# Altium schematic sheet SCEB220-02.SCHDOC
size A3
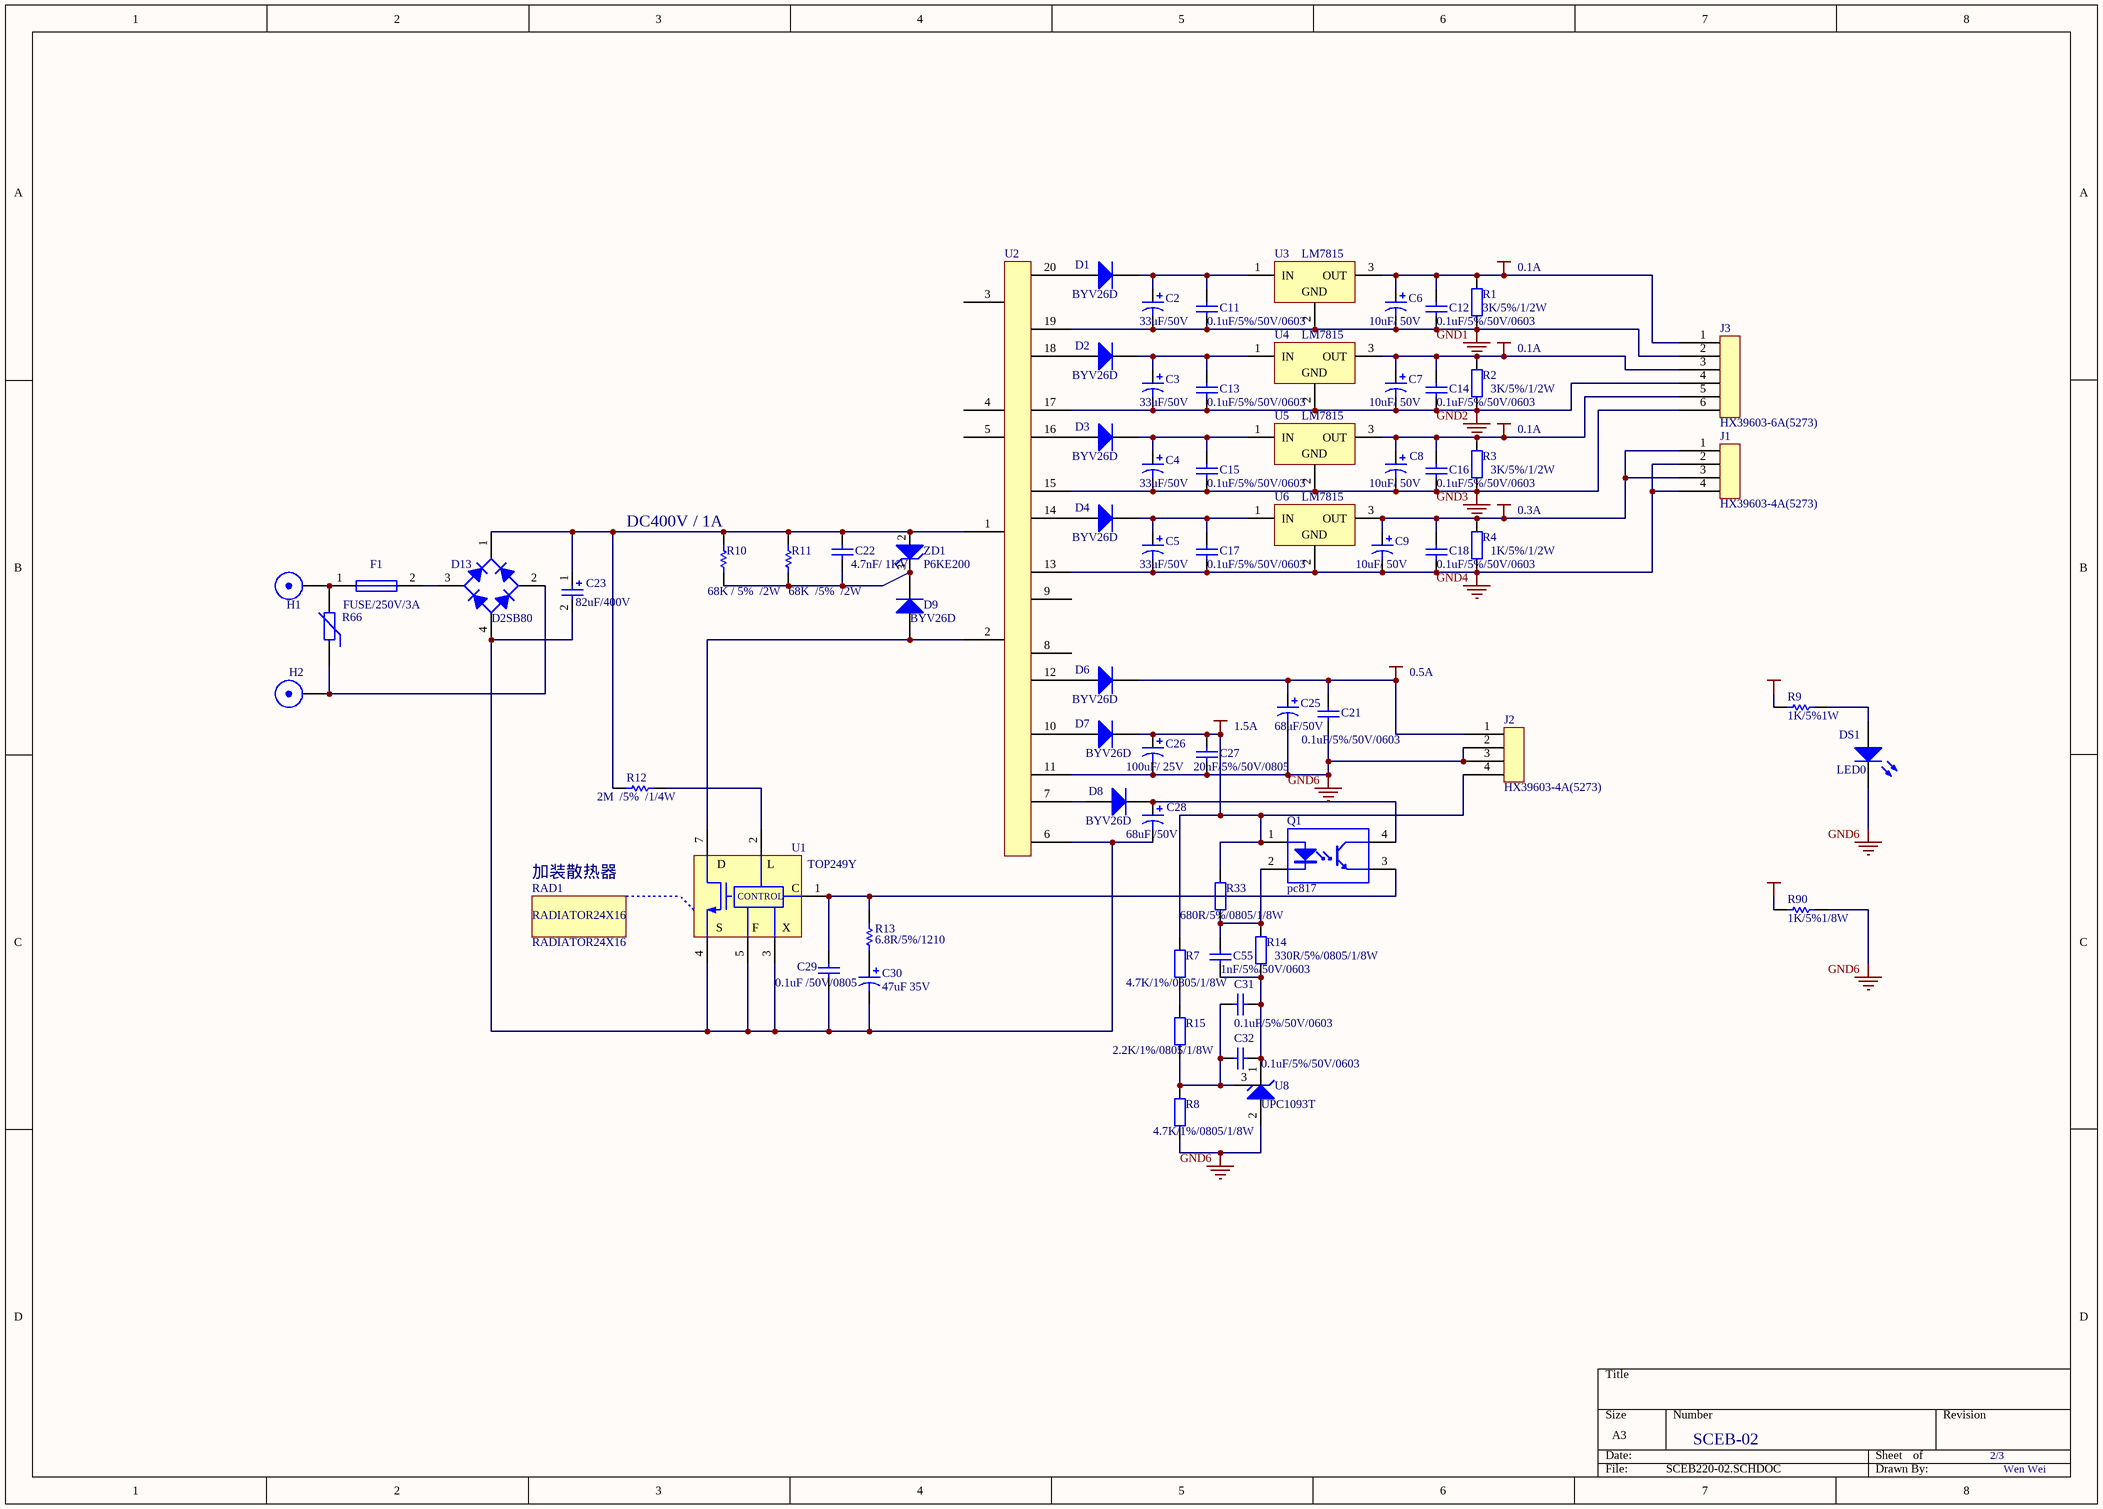
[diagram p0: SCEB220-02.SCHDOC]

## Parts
C2  value 33uF/50V  [CAP2.0-5X11]
C3  value 33uF/50V  [CAP2.0-5X11]
C4  value 33uF/50V  [CAP2.0-5X11]
C5  value 33uF/50V  [CAP2.0-5X11]
C6  10uF/ 50V  [CAP2.0-5X11]
C7  10uF/ 50V  [CAP2.0-5X11]
C8  10uF/ 50V  [CAP2.0-5X11]
C9  10uF/ 50V  [CAP2.0-5X11]
C11  0.1uF/50V/0603  [CR1608-0603]  (value not drawn)
C12  0.1uF/50V/0603  [CC2012-0805]  (value not drawn)
C13  0.1uF/50V/0603  [CC2012-0805]  (value not drawn)
C14  0.1uF/50V/0603  [CC2012-0805]  (value not drawn)
C15  0.1uF/50V/0603  [CC2012-0805]  (value not drawn)
C16  0.1uF/50V/0603  [CC2012-0805]  (value not drawn)
C17  0.1uF/50V/0603  [CC2012-0805]  (value not drawn)
C18  0.1uF/50V/0603  [CC2012-0805]  (value not drawn)
C21  0.1uF/50V/0603  [CC2012-0805]  (value not drawn)
C22  4.7nF/ 1KV  [RAD-0.3]
C23  URZ2G270MHH3  [CAPP10-22x25]  (value not drawn)
C25  68uF/50V  [CAP3.5-8X11.5]
C26  100uF/ 25V  [CAP3.5-8X11.5]
C27  (no value)  [CC2012-0805]
C28  68uF /50V  [CAP3.5-8X11.5]
C29  0.1uF /50V/0805  [CC2012-0805]
C30  47uF 35V  [CAPP2-5x11]
C31  0.1uF/5%/50V/0603  [CC2012-0805]
C32  0.1uF/5%/50V/0603  [CC2012-0805]
C55  1nF/5%/50V/0603  [CC2012-0805]
D1  BYV26D  [DIO7.1-3.9x1.9]
D2  BYV26D  [DIO7.1-3.9x1.9]
D3  BYV26D  [DIO7.1-3.9x1.9]
D4  BYV26D  [DIO7.1-3.9x1.9]
D6  BYV26D  [DIO7.1-3.9x1.9]
D7  BYV26D  [DIO7.1-3.9x1.9]
D8  BYV26D  [DIO7.1-3.9x1.9]
D9  BYV26D  [DIO-6]
D13  D2SB80  [D2SB80]
DS1  LED0  [DIO-2]
F1  FUSE/250V/3A  [F_KE]
H1  hanpan  [F_DIN]  (value not drawn)
H2  hanpan  [F_DIN]  (value not drawn)
J1  HX39603-4A(5273)  [HX39603-4A(5273)]
J2  HX39603-4A(5273)  [HX39603-4A(5273)]
J3  HX39603-6A(5273)  [HX39603-6A(5273)]
Q1  pc817  [DIP-4]
R1  3K/5%/1/2W  [RAD-0.3]
R2  value 3K/5%/1/2W  [RAD-0.3]
R3  value 3K/5%/1/2W  [RAD-0.3]
R4  value 1K/5%/1/2W  [RAD-0.4]
R7  value 4.7K/1%/0805/1/8W  [CR2012-0805]
R8  value 4.7K/1%/0805/1/8W  [CR2012-0805]
R9  1K/5%1W  [RAD-0.4]
R10  68K / 5%  /2W  [zlss-1]
R11  68K  /5%  /2W  [zlss-1]
R12  2M  /5%  /1/4W  [R10]
R13  6.8R/5%/1210  [CC3225-1210]
R14  value 330R/5%/0805/1/8W  [CR5025-2010]
R15  2.2K/1%/0805/1/8W  [CR2012-0805]
R33  value 680R/5%/0805/1/8W  [CR2012-0805]
R66  (no value)  [AXIAL-0.6]
R90  1K/5%1/8W  [RAD-0.3]
RAD1  RADIATOR24X16  [RADIATOR24X16]
U1  TOP249Y  [TO-220-7C]
U2  (no value)  [YNC07029]
U3  LM7815  [KC03]
U4  LM7815  [KC03]
U5  LM7815  [KC03]
U6  LM7815  [KC03]
U8  UPC1093T  [SOT89]
ZD1  P6KE200  [DIO-10]

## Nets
6.5V: C26.1 C27.2 D7.2 J2.4 Q1.1 R7.2 R33.2 R90.2
15V1: C6.1 C12.2 J3.1 R1.2 U3.3(OUT)
15V2: C7.1 C14.2 J3.3 R2.2 U4.3(OUT)
15V3: C8.1 C16.2 J3.5 R3.2 U5.3(OUT)
15V4: C9.1 C18.2 J1.1 J1.3 R4.2 U6.3(OUT)
24V: C21.2 C25.1 D6.2 J2.1 R9.2
GND1: C2.2 C6.2 C11.1 C12.1 J3.2 R1.1 U2.19 U3.2(GND)
GND2: C3.2 C7.2 C13.1 C14.1 J3.4 R2.1 U2.17 U4.2(GND)
GND3: C4.2 C8.2 C15.1 C16.1 J3.6 R3.1 U2.15 U5.2(GND)
GND4: C5.2 C9.2 C17.1 C18.1 J1.2 J1.4 R4.1 U2.13 U6.2(GND)
GND6: C21.1 C25.2 C26.2 C27.1 DS1.2(K) J2.2 J2.3 R8.1 R90.1 U2.11 U8.2(A)
NetC2_1: C2.1 C11.2 D1.2 U3.1(IN)
NetC3_1: C3.1 C13.2 D2.2 U4.1(IN)
NetC4_1: C4.1 C15.2 D3.2 U5.1(IN)
NetC5_1: C5.1 C17.2 D4.2 U6.1(IN)
NetC22_1: C22.1 D9.2(K) R10.2 R11.2 ZD1.3(K)
NetC22_2: C22.2 C23.1 D13.1 R10.1 R11.1 R12.2 U2.1 ZD1.2(A)
NetC23_2: C23.2 C28.2 C29.1 C30.2 D13.4 U1.3(X) U1.4(S) U1.5(F) U2.6
NetC28_1: C28.1 D8.2 Q1.4
NetC29_2: C29.2 Q1.3 R13.2 U1.1(C)
NetC30_1: C30.1 R13.1
NetC31_1: C31.1 C32.1 C55.2 R14.1 U8.1(K)
NetC31_2: C31.2 C32.2 R8.2 R15.1 U8.3
NetC55_1: C55.1 Q1.2 R14.2 R33.1
NetD1_1: D1.1 U2.20
NetD2_1: D2.1 U2.18
NetD3_1: D3.1 U2.16
NetD4_1: D4.1 U2.14
NetD6_1: D6.1 U2.12
NetD7_1: D7.1 U2.10
NetD8_1: D8.1 U2.7
NetD9_1: D9.1(A) U1.7(D) U2.2
NetD13_2: D13.2 H2.1(X) R66.1
NetD13_3: D13.3 F1.2
NetDS1_1: DS1.1(A) R9.1
NetF1_1: F1.1 H1.1(X) R66.2
NetR7_1: R7.1 R15.2
NetR12_1: R12.1 U1.2(L)

Not connected (* = marked no-connect by the designer): U2 3 4 5 8 9

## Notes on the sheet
- (near R1) 0.1A
- 0.1A
- 0.3A
- (near R10) DC400V / 1A
- 0.5A
- 1.5A
- (near RAD1) 加装散热器
- SCEB-02
- 2/3
- Wen Wei
- Labels drawn without touching a wire or pin: GND1, GND2, GND3, GND4, GND6

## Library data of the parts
C2-C5 = Cap Pol2: Polarized Capacitor (Axial)
C6-C9 C25 C26 C30 = Cap Pol2: Polarized Capacitor (Axial); Value: 100pF
C11-C18 C21 C27 = CAP_0603: Capacitor
C22 C29 = Cap: Capacitor
C23 = Cap3-8.4X20: Polarized Capacitor (Axial)
C28 = Cap Pol2: Polarized Capacitor (Axial); Value: 1uF
C31 C32 C55 = Cap: Capacitor; Value: 150nF
D1-D4 D6-D9 = Diode 1N4148: High Conductance Fast Diode
DS1 = LED0: Typical INFRARED GaAs LED
F1 = FUSE_33X7
Q1 = ps2701-1
R1-R4 R7 R8 R14 R15 R33 = Res2: Resistor
R9 R90 = RES_0805: Resistor
R10 R11 = RES_1210: Resistor
R12 = RES_1210
R13 = Res1: Resistor; Value: 6.8R
R66 = Res Varistor: Varistor (Voltage-Sensitive Resistor)
U2 = Component_3
U3-U6 = LM2930-8KC: 3-Terminal Positive Regulator
ZD1 = DIODE RD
